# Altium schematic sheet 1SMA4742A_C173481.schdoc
size 127 x 101 mm
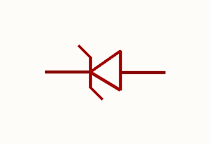
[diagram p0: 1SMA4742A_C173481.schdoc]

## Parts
D?  1sma4742a_c173481  [SMA_L4.4-W2.8-LS5.4-RD]  (value not drawn)

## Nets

Not connected (* = marked no-connect by the designer): D? 1 2

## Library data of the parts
D? = 1sma4742a_c173481: 二极管配置:1个独立式;稳压值(标称值):12V;稳压值(范围):11.4V~12.6V;耗散功率(Pd):1W;; Manufacturer: MDD(辰达半导体); AddInBom: yes; ModelId: 4f1e9ef2303f48b48aa8ce0cacf8d7b1; ModelTransform: 204.724,102.362,0,0,0,0,0,0,0; Diode Configuration: 1个独立式; Zener Voltage(Nom): 12V; Reverse Leakage Current (Ir): 5uA; Pd - Power Dissipation: 1W; Impedance(Zzt): 9Ω; Operating Junction Temperature Range: -55℃~+150℃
